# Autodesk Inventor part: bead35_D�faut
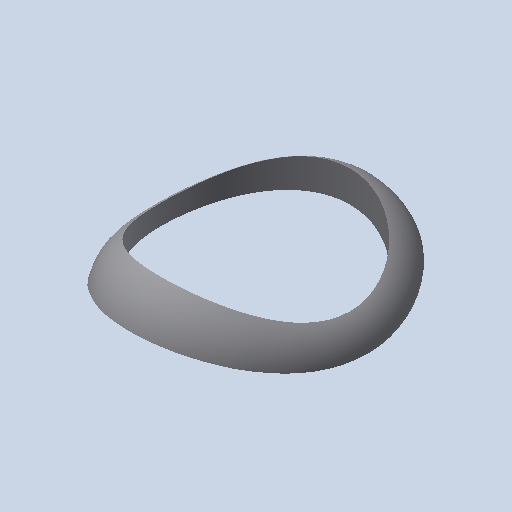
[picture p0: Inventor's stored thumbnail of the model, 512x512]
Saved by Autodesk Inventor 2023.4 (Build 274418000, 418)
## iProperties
Created: 2011-01
Part Number: bead35_D�faut
Document SubType Name: Modeling
Designer: eric
Density: 1 g/cm^3
Mass: 0.0717213 g
Surface Area: 2.4299 cm^2
Volume: 0.0717213 cm^3
Material: Générique
Appearance: Par défaut
Author: eric
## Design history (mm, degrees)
feature "Base1"
node "Corps solides"
node "Corps surfaciques"
node "Solide1"
